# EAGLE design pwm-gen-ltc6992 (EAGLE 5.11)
PID: 921
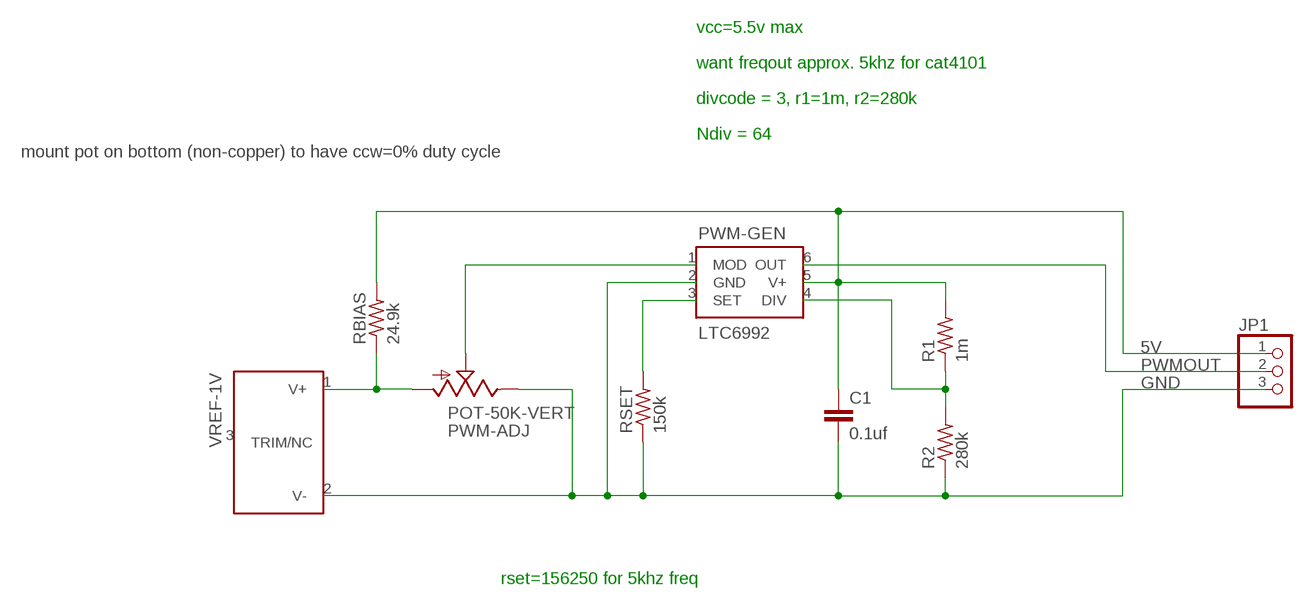
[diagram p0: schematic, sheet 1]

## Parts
C1  0.1uf  C-EUC0805  [C0805]
JP1  PINHD-1X3  [1X03]
PWM-ADJ  POT-50K-VERT  POT-TRIM-0.35IN  [POT-TRIM-0.35IN]
PWM-GEN  LTC6992  [SOT-23-6]
R1  1m  R-US_M0805  [M0805]
R2  280k  R-US_M0805  [M0805]
RBIAS  24.9k  R-US_M0805  [M0805]
RSET  150k  R-US_M0805  [M0805]
VREF-1V  ADR510  [SOT23-3]

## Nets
5V: C1.1 JP1.1 PWM-GEN.5(V+) R1.2 RBIAS.2
GND: C1.2 JP1.3 PWM-ADJ.3(E) PWM-GEN.2(GND) R2.1 RSET.1 VREF-1V.2(V-)
N$3: PWM-GEN.4(DIV) R1.1 R2.2
N$4: PWM-ADJ.1(A) RBIAS.1 VREF-1V.1(V+)
N$5: PWM-ADJ.2(S) PWM-GEN.1(MOD)
N$7: PWM-GEN.3(SET) RSET.2
PWMOUT: JP1.2 PWM-GEN.6(OUT)
Unconnected: VREF-1V.3(TRIM/NC)

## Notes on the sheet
- vcc=5.5v max
- want freqout approx. 5khz for cat4101
- divcode = 3, r1=1m, r2=280k
- Ndiv = 64
- mount pot on bottom (non-copper) to have ccw=0% duty cycle
- rset=156250 for 5khz freq

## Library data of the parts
C1 = rcl:C-EU: CAPACITOR, European symbol
JP1 = pinhead:PINHD-1X3: PIN HEADER
PWM-ADJ = trl:POT-TRIM-0.35IN
PWM-GEN = trl:LTC6992
R1 R2 RBIAS RSET = resistor:R-US_: RESISTOR, American symbol
VREF-1V = trl:ADR510

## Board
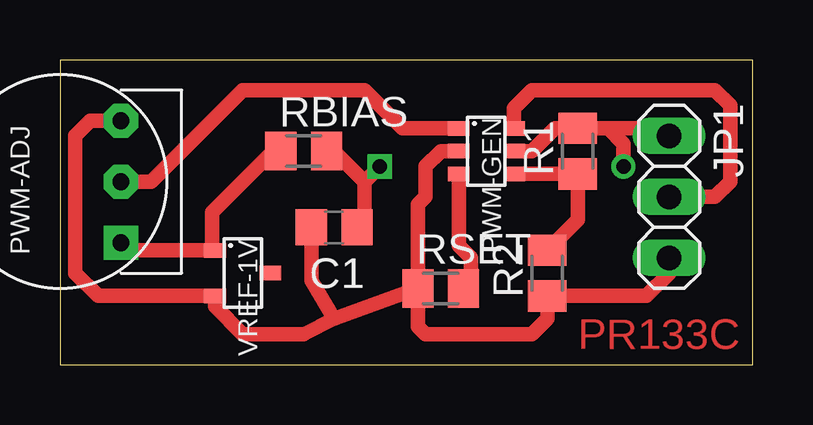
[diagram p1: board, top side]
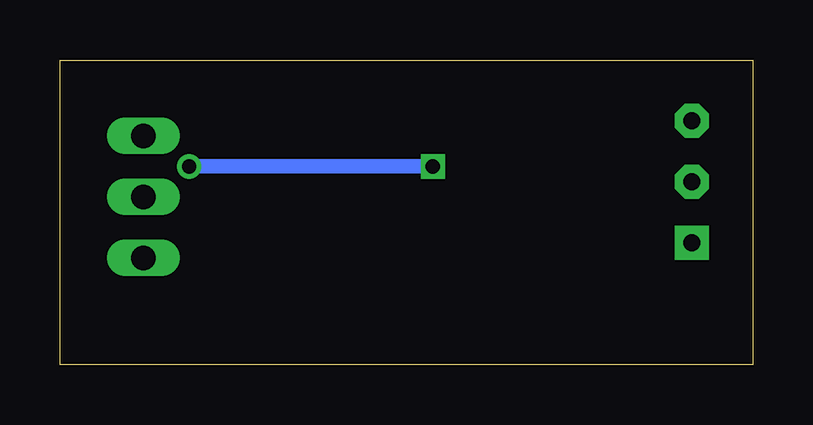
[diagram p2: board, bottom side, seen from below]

Size 28.88 x 12.69 mm. Coordinates in mm from the lower left corner, seen from the top.
Outline: 0,0 28.88,0 28.88,12.69 0,12.69 0,0
Copper layers (1*16): Top 0.035mm / dielectric 1.5mm / Bottom 0.035mm
Design rules "default": minimum track width 10mil, minimum drill 24mil, track to track 8mil, track to pad 8mil, pad to pad 8mil, via to via 8mil, smd to smd 8mil, copper to edge 40mil, drill to drill 8mil, minimum pad ring 10mil, minimum via ring 8mil, stop-mask expansion 4mil, vias tented up to drill 0mil, thermal gap 10mil

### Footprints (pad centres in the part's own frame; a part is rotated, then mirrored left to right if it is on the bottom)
C0805 = smd 1.3 x 1.5: 1 -0.95,0; 2 0.95,0
1X03 = drill 1.016 long: 1 -2.54,0; 2 0,0; 3 2.54,0
POT-TRIM-0.35IN = drill 0.7 pad 1.422 square: 1 -2.54,-3.81 | drill 0.7 pad 1.422 octagon: 2 0,-3.81; 3 2.54,-3.81
SOT-23-6 = smd 0.6 x 0.9: 1 -0.95,-1.15; 2 0,-1.15; 3 0.95,-1.15; 4 0.95,1.15; 5 0,1.15; 6 -0.95,1.15
M0805 = smd 1.3 x 1.6: 1 -0.95,0; 2 0.95,0
SOT23-3 = smd 0.6 x 0.9: 1 -0.95,-1.15; 2 0.95,-1.15; 3 0,1.15

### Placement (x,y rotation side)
C1  11.43,5.71 180 top
JP1  25.4,6.99 270 top
PWM-ADJ  -1.27,7.62 90 top
PWM-GEN  17.78,8.89 270 top
R1  21.59,8.89 90 top
R2  20.32,3.81 90 top
RBIAS  10.16,8.89 0 top
RSET  15.88,3.17 0 top
VREF-1V  7.62,3.81 270 top

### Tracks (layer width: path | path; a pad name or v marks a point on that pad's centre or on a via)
5V  (via drill 0.6)
  Top 0.61: RBIAS.2 11.43,8.89 12.7,7.62 | 12.7,7.62 12.7,6.04 C1.1 | 22.86,9.84 R1.2 20.64,9.84 19.68,8.89 PWM-GEN.5 | 22.86,9.84 25.09,9.84 JP1.1 | 12.7,7.62 v13.34,8.26 | v23.5,8.26 23.5,9.21 22.86,9.84
  Bottom 0.61: v13.34,8.26 v23.5,8.26
GND
  Top 0.61: PWM-ADJ.3 1.27,10.16 0.64,9.53 0.64,3.81 1.58,2.86 VREF-1V.2 6.47,2.42 7.62,1.27 10.16,1.27 11.43,1.91 | C1.2 10.48,3.49 11.43,1.91 | 11.43,1.91 RSET.1 | RSET.1 14.93,6.67 15.24,6.99 15.24,8.26 15.88,8.89 PWM-GEN.2 | JP1.3 25.4,3.81 24.45,2.86 R2.1 20.32,1.91 19.68,1.27 15.24,1.27 14.93,1.58 RSET.1
N$3
  Top 0.61: R2.2 21.59,6.03 R1.1 PWM-GEN.4
N$4
  Top 0.61: PWM-ADJ.1 2.86,4.76 VREF-1V.1 6.35,4.88 6.35,6.35 8.89,8.89 RBIAS.1
N$5
  Top 0.61: PWM-GEN.1 14.29,9.84 12.7,11.43 7.62,11.43 3.81,7.62 PWM-ADJ.2
N$7
  Top 0.61: PWM-GEN.3 16.63,4.96 17.14,4.45 17.14,3.5 RSET.2
PWMOUT
  Top 0.61: PWM-GEN.6 18.93,10.68 19.68,11.43 27.3,11.43 27.94,10.79 27.94,7.62 27.3,6.99 JP1.2

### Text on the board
Top: PR133C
